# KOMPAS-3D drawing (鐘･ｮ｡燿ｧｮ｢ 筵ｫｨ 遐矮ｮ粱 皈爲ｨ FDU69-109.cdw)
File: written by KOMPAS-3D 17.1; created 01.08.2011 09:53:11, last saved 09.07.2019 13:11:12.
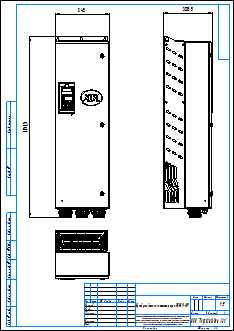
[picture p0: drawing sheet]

Title block, sheet 1: name: Преобразователи частоты серии FDU69-109; scale: 1:5; sheets: 1; sheet format: A3; stored path: \\adlc.lan\data\АДЛ_ПКД\3D-модели\Поставщики\Оборудование Emotron\Преобразователи частоты\Серия FDU 2.0\KOMPAS 2D\Преобразователи частоты серии FDU69-109.cdw

Views: Спереди 1
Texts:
  Рама для чертежей
  Лит-Масса-Масштаб
  Материал-Предприятие
  Масштаб
  Изм.
  Лист
  № докум.
  Подп.
  Дата
  Лит.
  Разраб.
  Пров.
  Т.контр.
  Листов
  Внимание! Данный продукт является объектом авторского права ООО «Торговый Дом АДЛ».
  Запрещается изменение, копирование, распространение
  (в том числе путем копирования на другие сайты и ресурсы в Интернете)
  или любое иное использование информации и объектов без предварительного
  согласия правообладателя (ООО «Торговый Дом АДЛ»).
  Н.контр.
  Утв.
  ООО "Торговый дом АДЛ"
  Изменение
  Номер документа
  Подпись
  Обозначение документа
  Наименование изделия
  Масса изделия по ГОСТ 2.109-73
  Порядковый номер листа
  Общее количество листов в документе
  Характер работы, выполненной лицом, подписавшим документ
  Наименование или индекс предприятия, выпускающего документ
  Инв. № подл.
  Подп. и дата
  Взам. инв. №
  Инв. № дубл.
  Инвентарный номер подлинника по ГОСТ 2.501-68
  Подпись принявшего подлинник в отдел технической документации
  Инвентарный номер подлинника, взамен которого выпущен данный подлинник
  Инвентарный номер дубликата по ГОСТ 2.502-68
  Подпись принявшего дубликат в отдел технической документации
  Справ. №
  Перв. примен.
  Обозначение документа, взамен или на основании которого выпущен данный документ
  Обозначение документа, в котором впервые записан данный документ
  Подпись лица, копировавшего чертеж
  Обозначение формата листа
  !Рама для чертежа
Dimensions and other numbers on the sheet: 1151,5; 345; 308,5; 1:5; 1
